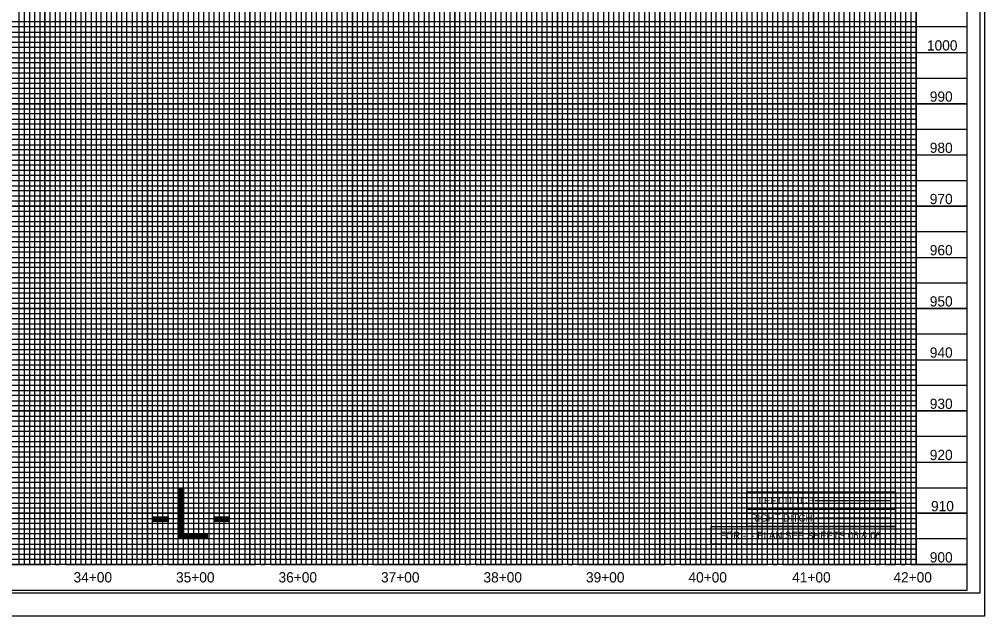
# Model space of a CAD drawing. Extents: x 1262239 to 1263984, y 747221 to 748321.
# Drawn here: x 1262981 to 1263923, y 747221 to 747803 of the extents above; entities that cross this region are included whole.
import ezdxf

# ---------------------------------------------------------------- set-up
doc = ezdxf.new("R2010")
doc.units = 0
for name, color, linetype in [('Pattern 1', 7, 'Continuous'), ('Pattern 2', 7, 'Continuous'), ('Prop Approach Slab', 7, 'Continuous'), ('Prop Drainage Structure Bridge Opening', 7, 'Continuous'), ('Prop Drainage Structure Bridge Opening Label', 7, 'Continuous'), ('Prop Erosion Rip Rap Single Stone CELL', 7, 'Continuous'), ('Prop Grid Mask', 7, 'Continuous'), ('Prop Horizontal Alignment Curve and Spiral Data', 7, 'Continuous'), ('Prop Paved Shoulder', 7, 'Continuous'), ('Prop PFL Text', 7, 'Continuous'), ('Prop Terminator CELL', 7, 'Continuous'), ('Prop Vertical Profile Strip Grade', 7, 'Continuous'), ('Prop VPI Label', 7, 'Continuous'), ('Sheet Border Standard 30in CELL', 7, 'Continuous'), ('Sheet Profile Grid Middle CELL', 7, 'Continuous'), ('Sheet Sticker Exception Certification CELL', 7, 'Continuous')]:
    doc.layers.add(name, color=color, linetype=linetype)

msp = doc.modelspace()

# ---------------------------------------------------------------- linework, layer by layer
at = {"layer": 'Pattern 1'}
for points in [[(1262955.75, 747270.74), (1263005.75, 747270.74), (1263005.75, 748295.74)], [(1263055.75, 748295.74), (1263055.75, 747270.74), (1263105.75, 747270.74), (1263105.75, 748295.74)], [(1263155.75, 748295.74), (1263155.75, 747270.74), (1263205.75, 747270.74), (1263205.75, 748295.74)], [(1263255.75, 748295.74), (1263255.75, 747270.74), (1263305.75, 747270.74), (1263305.75, 748295.74)], [(1263355.75, 748295.74), (1263355.75, 747270.74), (1263405.75, 747270.74), (1263405.75, 748295.74)], [(1263455.75, 748295.74), (1263455.75, 747270.74), (1263505.75, 747270.74), (1263505.75, 748295.74)], [(1263555.75, 748295.74), (1263555.75, 747270.74), (1263605.75, 747270.74), (1263605.75, 748245.74)], [(1263655.75, 748245.74), (1263655.75, 747270.74), (1263705.75, 747270.74), (1263705.75, 748245.74)], [(1263755.75, 748134.69), (1263755.75, 747270.74), (1263805.75, 747270.74), (1263805.75, 748134.69)], [(1263855.75, 748134.69), (1263855.75, 747270.74), (1263905.75, 747270.74)], [(1263905.75, 747720.74), (1262405.75, 747720.74), (1262405.75, 747770.74), (1263905.75, 747770.74)], [(1263905.75, 747620.74), (1262405.75, 747620.74), (1262405.75, 747670.74), (1263905.75, 747670.74)], [(1263905.75, 747520.74), (1262405.75, 747520.74), (1262405.75, 747570.74), (1263905.75, 747570.74)], [(1263905.75, 747420.74), (1262405.75, 747420.74), (1262405.75, 747470.74), (1263905.75, 747470.74)], [(1263905.75, 747320.74), (1262405.75, 747320.74), (1262405.75, 747370.74), (1263905.75, 747370.74)]]:
    msp.add_lwpolyline(points, dxfattribs=at)
at = {"layer": 'Pattern 2'}
for points in [[(1262930.75, 747270.74), (1262980.75, 747270.74), (1262980.75, 748295.74)], [(1263030.75, 748295.74), (1263030.75, 747270.74), (1263080.75, 747270.74), (1263080.75, 748295.74)], [(1263130.75, 748295.74), (1263130.75, 747270.74), (1263180.75, 747270.74), (1263180.75, 748295.74)], [(1263230.75, 748295.74), (1263230.75, 747270.74), (1263280.75, 747270.74), (1263280.75, 748295.74)], [(1263330.75, 748295.74), (1263330.75, 747270.74), (1263380.75, 747270.74), (1263380.75, 748295.74)], [(1263430.75, 748295.74), (1263430.75, 747270.74), (1263480.75, 747270.74), (1263480.75, 748295.74)], [(1263530.75, 748295.74), (1263530.75, 747270.74), (1263580.75, 747270.74), (1263580.75, 748295.74)], [(1263630.75, 748245.74), (1263630.75, 747270.74), (1263680.75, 747270.74), (1263680.75, 748245.74)], [(1263730.75, 748134.69), (1263730.75, 747270.74), (1263780.75, 747270.74), (1263780.75, 748134.69)], [(1263830.75, 748134.69), (1263830.75, 747270.74)], [(1263905.75, 747795.74), (1262405.75, 747795.74), (1262405.75, 747745.74), (1263905.75, 747745.74)], [(1263905.75, 747695.74), (1262405.75, 747695.74), (1262405.75, 747645.74), (1263905.75, 747645.74)], [(1263905.75, 747595.74), (1262405.75, 747595.74), (1262405.75, 747545.74), (1263905.75, 747545.74)], [(1263905.75, 747495.74), (1262405.75, 747495.74), (1262405.75, 747445.74), (1263905.75, 747445.74)], [(1263905.75, 747395.74), (1262405.75, 747395.74), (1262405.75, 747345.74), (1263905.75, 747345.74)], [(1263905.75, 747295.74), (1262405.75, 747295.74)]]:
    msp.add_lwpolyline(points, dxfattribs=at)
at = {"layer": 'Prop Approach Slab'}
msp.add_line((1263757.4, 747316.24), (1263830.39, 747316.24), dxfattribs=at)
at = {"layer": 'Prop Drainage Structure Bridge Opening'}
msp.add_line((1262238.75, 747220.74), (1263922.75, 747220.74), dxfattribs=at)
at = {"layer": 'Prop Drainage Structure Bridge Opening Label'}
msp.add_line((1263757.36, 747333.24), (1263830.35, 747333.24), dxfattribs=at)
at = {"layer": 'Prop Erosion Rip Rap Single Stone CELL'}
for points in [[(1263690.75, 747341.74), (1263835.71, 747341.74), (1263835.71, 747324.74), (1263690.75, 747324.74)], [(1263690.75, 747324.74), (1263835.75, 747324.74), (1263835.75, 747307.74), (1263690.75, 747307.74)]]:
    msp.add_lwpolyline(points, close=True, dxfattribs=at)
at = {"layer": 'Prop Grid Mask'}
msp.add_lwpolyline([(1262455.75, 748295.74), (1263705.7, 748295.74), (1263705.7, 748134.69), (1263855.75, 748134.69), (1263855.75, 747270.74), (1262455.75, 747270.74)], close=True, dxfattribs=at)
at = {"layer": 'Prop Paved Shoulder'}
msp.add_line((1263905.75, 747270.74), (1262405.75, 747270.74), dxfattribs=at)
msp.add_lwpolyline([(1263905.75, 748295.74), (1262405.75, 748295.74), (1262405.75, 747245.74), (1263905.75, 747245.74)], close=True, dxfattribs=at)
at = {"layer": 'Prop PFL Text'}
for p, q in [((1263005.75, 748295.74), (1263005.75, 747270.74)), ((1263055.75, 748295.74), (1263055.75, 747270.74)), ((1263105.75, 748295.74), (1263105.75, 747270.74)), ((1263155.75, 748295.74), (1263155.75, 747270.74)), ((1263205.75, 748295.74), (1263205.75, 747270.74)), ((1263255.75, 748295.74), (1263255.75, 747270.74)), ((1263305.75, 748295.74), (1263305.75, 747270.74)), ((1263355.75, 748295.74), (1263355.75, 747270.74)), ((1263405.75, 748295.74), (1263405.75, 747270.74)), ((1263455.75, 748295.74), (1263455.75, 747270.74)), ((1263505.75, 748295.74), (1263505.75, 747270.74)), ((1263555.75, 748295.74), (1263555.75, 747270.74)), ((1263605.75, 748295.74), (1263605.75, 747270.74)), ((1263655.75, 748245.74), (1263655.75, 747270.74)), ((1263705.75, 747270.74), (1263705.75, 748158.19)), ((1263755.75, 747270.74), (1263755.75, 748134.69)), ((1263805.75, 747270.74), (1263805.75, 748134.69)), ((1263855.75, 747270.74), (1263855.75, 748134.69)), ((1262405.75, 747770.74), (1263905.75, 747770.74)), ((1262405.75, 747720.74), (1263905.75, 747720.74)), ((1262405.75, 747670.74), (1263905.75, 747670.74)), ((1262405.75, 747620.74), (1263905.75, 747620.74)), ((1262405.75, 747570.74), (1263905.75, 747570.74)), ((1262405.75, 747520.74), (1263905.75, 747520.74)), ((1262405.75, 747470.74), (1263905.75, 747470.74)), ((1262405.75, 747420.74), (1263905.75, 747420.74)), ((1262405.75, 747370.74), (1263905.75, 747370.74)), ((1262405.75, 747320.74), (1263905.75, 747320.74))]:
    msp.add_line(p, q, dxfattribs=at)
at = {"layer": 'Prop Terminator CELL'}
msp.add_lwpolyline([(1263918.25, 748298.29), (1262251.75, 748298.29), (1262251.75, 747243.19), (1263918.25, 747243.19)], close=True, dxfattribs=at)
at = {"layer": 'Prop VPI Label'}
msp.add_lwpolyline([(1263922.75, 748320.74), (1262238.75, 748320.74), (1262238.75, 747220.74), (1263922.75, 747220.74)], close=True, dxfattribs=at)
at = {"layer": 'Sheet Profile Grid Middle CELL'}
msp.add_lwpolyline([(1263655.75, 747307.74), (1263835.75, 747307.74), (1263835.75, 747290.74), (1263655.75, 747290.74)], close=True, dxfattribs=at)
at = {"layer": 'Sheet Sticker Exception Certification CELL'}
for points in [[(1262985.75, 747270.74), (1262985.75, 748295.74)], [(1262990.75, 748295.74), (1262990.75, 747270.74), (1262995.75, 747270.74), (1262995.75, 748295.74)], [(1263000.75, 748295.74), (1263000.75, 747270.74), (1263010.75, 747270.74), (1263010.75, 748295.74)], [(1263015.75, 748295.74), (1263015.75, 747270.74), (1263015.75, 747270.74), (1263020.75, 747270.74), (1263020.75, 748295.74)], [(1263025.75, 748295.74), (1263025.75, 747270.74), (1263035.75, 747270.74), (1263035.75, 748295.74)], [(1263040.75, 748295.74), (1263040.75, 747270.74), (1263045.75, 747270.74), (1263045.75, 748295.74)], [(1263050.75, 748295.74), (1263050.75, 747270.74), (1263060.75, 747270.74), (1263060.75, 748295.74)], [(1263065.75, 748295.74), (1263065.75, 747270.74), (1263070.75, 747270.74), (1263070.75, 748295.74)], [(1263075.75, 748295.74), (1263075.75, 747270.74), (1263085.75, 747270.74), (1263085.75, 748295.74)], [(1263090.75, 748295.74), (1263090.75, 747270.74), (1263095.75, 747270.74), (1263095.75, 748295.74)], [(1263100.75, 748295.74), (1263100.75, 747270.74), (1263110.75, 747270.74), (1263110.75, 748295.74)], [(1263115.75, 748295.74), (1263115.75, 747270.74), (1263120.75, 747270.74), (1263120.75, 748295.74)], [(1263125.75, 748295.74), (1263125.75, 747270.74), (1263135.75, 747270.74), (1263135.75, 748295.74)], [(1263140.75, 748295.74), (1263140.75, 747270.74), (1263145.75, 747270.74), (1263145.75, 748295.74)], [(1263150.75, 748295.74), (1263150.75, 747270.74), (1263160.75, 747270.74), (1263160.75, 748295.74)], [(1263165.75, 748295.74), (1263165.75, 747270.74)], [(1263165.75, 747270.74), (1263170.75, 747270.74), (1263170.75, 748295.14)], [(1263175.75, 748295.14), (1263175.75, 747270.74), (1263185.75, 747270.74), (1263185.75, 748295.74)], [(1263190.75, 748295.74), (1263190.75, 747270.74), (1263195.75, 747270.74), (1263195.75, 748295.74)], [(1263200.75, 748295.74), (1263200.75, 747270.74), (1263210.75, 747270.74), (1263210.75, 748295.74)], [(1263215.75, 748295.74), (1263215.75, 747270.74), (1263220.75, 747270.74), (1263220.75, 748295.74)], [(1263225.75, 748295.74), (1263225.75, 747270.74), (1263235.75, 747270.74), (1263235.75, 748295.74)], [(1263240.75, 748295.74), (1263240.75, 747270.74), (1263245.75, 747270.74), (1263245.75, 748295.74)], [(1263250.75, 748295.74), (1263250.75, 747270.74), (1263260.75, 747270.74), (1263260.75, 748295.74)], [(1263265.75, 748295.74), (1263265.75, 747270.74), (1263270.75, 747270.74), (1263270.75, 748295.74)], [(1263275.75, 748295.74), (1263275.75, 747270.74), (1263285.75, 747270.74), (1263285.75, 748295.74)], [(1263290.75, 748295.74), (1263290.75, 747270.74), (1263295.75, 747270.74), (1263295.75, 748295.74)], [(1263300.75, 748295.74), (1263300.75, 747270.74), (1263310.75, 747270.74), (1263310.75, 748295.74)], [(1263315.75, 748295.74), (1263315.75, 747270.74), (1263320.75, 747270.74), (1263320.75, 748295.74)], [(1263325.75, 748295.74), (1263325.75, 747270.74), (1263335.75, 747270.74), (1263335.75, 748295.74)], [(1263340.75, 748295.74), (1263340.75, 747270.74), (1263345.75, 747270.74), (1263345.75, 748295.74)], [(1263350.75, 748295.74), (1263350.75, 747270.74), (1263360.75, 747270.74), (1263360.75, 748295.74)], [(1263365.75, 748295.74), (1263365.75, 747270.74), (1263370.75, 747270.74), (1263370.75, 748295.74)], [(1263375.75, 748295.74), (1263375.75, 747270.74), (1263385.75, 747270.74), (1263385.75, 748295.74)], [(1263390.75, 748295.74), (1263390.75, 747270.74), (1263395.75, 747270.74), (1263395.75, 748295.74)], [(1263400.75, 748295.74), (1263400.75, 747270.74), (1263410.75, 747270.74), (1263410.75, 748295.74)], [(1263415.75, 748295.74), (1263415.75, 747270.74), (1263420.75, 747270.74), (1263420.75, 748295.74)], [(1263425.75, 748295.74), (1263425.75, 747270.74), (1263435.75, 747270.74), (1263435.75, 748295.74)], [(1263440.75, 748295.74), (1263440.75, 747270.74), (1263445.75, 747270.74), (1263445.75, 748295.74)], [(1263450.75, 748295.74), (1263450.75, 747270.74), (1263460.75, 747270.74), (1263460.75, 748295.74)], [(1263465.75, 748295.74), (1263465.75, 747270.74), (1263470.75, 747270.74), (1263470.75, 748295.74)], [(1263475.75, 748295.74), (1263475.75, 747270.74)], [(1263475.75, 747270.74), (1263485.75, 747270.74), (1263485.75, 748295.74)], [(1263490.75, 748295.74), (1263490.75, 747270.74), (1263495.75, 747270.74), (1263495.75, 748295.74)], [(1263500.75, 748295.74), (1263500.75, 747270.74), (1263510.75, 747270.74), (1263510.75, 748295.74)], [(1263515.75, 748295.74), (1263515.75, 747270.74), (1263520.75, 747270.74), (1263520.75, 748295.74)], [(1263525.75, 748295.74), (1263525.75, 747270.74), (1263535.75, 747270.74), (1263535.75, 748295.74)], [(1263540.75, 748295.74), (1263540.75, 747270.74), (1263545.75, 747270.74), (1263545.75, 748295.74)], [(1263550.75, 748295.74), (1263550.75, 747270.74), (1263560.75, 747270.74), (1263560.75, 748295.74)], [(1263565.75, 748295.74), (1263565.75, 747270.74), (1263570.75, 747270.74), (1263570.75, 748295.74)], [(1263575.75, 748295.74), (1263575.75, 747270.74), (1263585.75, 747270.74), (1263585.75, 748295.74)], [(1263590.75, 748295.74), (1263590.75, 747270.74), (1263595.75, 747270.74), (1263595.75, 748295.74)], [(1263600.75, 748295.74), (1263600.75, 747270.74), (1263610.75, 747270.74), (1263610.75, 748245.74)], [(1263615.75, 748245.74), (1263615.75, 747270.74), (1263620.75, 747270.74), (1263620.75, 748245.74)], [(1263625.75, 748245.74), (1263625.75, 747270.74), (1263635.75, 747270.74), (1263635.75, 748245.74)], [(1263640.75, 748245.74), (1263640.75, 747270.74), (1263645.75, 747270.74), (1263645.75, 748245.74)], [(1263650.75, 748245.74), (1263650.75, 747270.74), (1263660.75, 747270.74), (1263660.75, 748245.74)], [(1263665.75, 748245.74), (1263665.75, 747270.74), (1263670.75, 747270.74), (1263670.75, 748245.74)], [(1263675.75, 748245.74), (1263675.75, 747270.74), (1263685.75, 747270.74), (1263685.75, 748245.74)], [(1263690.75, 748245.74), (1263690.75, 747270.74), (1263695.75, 747270.74), (1263695.75, 748245.74)], [(1263700.75, 748245.74), (1263700.75, 747270.74), (1263710.75, 747270.74), (1263710.75, 748134.69)], [(1263715.75, 748134.69), (1263715.75, 747270.74), (1263720.75, 747270.74), (1263720.75, 748134.69)], [(1263725.75, 748134.69), (1263725.75, 747270.74), (1263735.75, 747270.74), (1263735.75, 748134.69)], [(1263740.75, 748134.69), (1263740.75, 747270.74), (1263745.75, 747270.74), (1263745.75, 748134.69)], [(1263750.75, 748134.69), (1263750.75, 747270.74), (1263760.75, 747270.74), (1263760.75, 748134.69)], [(1263765.75, 748134.69), (1263765.75, 747270.74), (1263770.75, 747270.74), (1263770.75, 748134.69)], [(1263775.75, 748134.69), (1263775.75, 747270.74), (1263785.75, 747270.74), (1263785.75, 748134.69)], [(1263790.75, 748134.69), (1263790.75, 747270.74)], [(1263790.75, 747270.74), (1263795.75, 747270.74), (1263795.75, 748134.69)], [(1263800.75, 748134.69), (1263800.75, 747270.74), (1263810.75, 747270.74), (1263810.75, 748134.69)], [(1263815.75, 748134.69), (1263815.75, 747270.74), (1263820.75, 747270.74), (1263820.75, 748134.69)], [(1263825.75, 748134.69), (1263825.75, 747270.74), (1263835.75, 747270.74), (1263835.75, 748134.69)], [(1263840.75, 748134.69), (1263840.75, 747270.74), (1263845.75, 747270.74), (1263845.75, 748134.69)], [(1263850.75, 748134.69), (1263850.75, 747270.74), (1263860.75, 747270.74)], [(1263855.75, 747800.74), (1262455.75, 747800.74), (1262455.75, 747790.74), (1263855.75, 747790.74)], [(1263855.75, 747785.74), (1262455.75, 747785.74), (1262455.75, 747780.74), (1263855.75, 747780.74)], [(1263855.75, 747775.74), (1262455.75, 747775.74)], [(1262455.75, 747765.74), (1263855.75, 747765.74)], [(1263855.75, 747760.74), (1262455.75, 747760.74), (1262455.75, 747755.74), (1263855.75, 747755.74)], [(1263855.75, 747750.74), (1262455.75, 747750.74), (1262455.75, 747740.74), (1263855.75, 747740.74)], [(1263855.75, 747735.74), (1262455.75, 747735.74), (1262455.75, 747730.74), (1263855.75, 747730.74)], [(1263855.75, 747725.74), (1262455.75, 747725.74), (1262455.75, 747715.74), (1263855.75, 747715.74)], [(1263855.75, 747710.74), (1262455.75, 747710.74), (1262455.75, 747705.74), (1263855.75, 747705.74)], [(1263855.75, 747700.74), (1262455.75, 747700.74), (1262455.75, 747690.74), (1263855.75, 747690.74)], [(1263855.75, 747685.74), (1262455.75, 747685.74), (1262455.75, 747680.74), (1263855.75, 747680.74)], [(1263855.75, 747675.74), (1262455.75, 747675.74), (1262455.75, 747665.74), (1263855.75, 747665.74)], [(1263855.75, 747660.74), (1262455.75, 747660.74), (1262455.75, 747655.74), (1263855.75, 747655.74)], [(1263855.75, 747650.74), (1262455.75, 747650.74), (1262455.75, 747640.74), (1263855.75, 747640.74)], [(1263855.75, 747635.74), (1262455.75, 747635.74), (1262455.75, 747630.74), (1263855.75, 747630.74)], [(1263855.75, 747625.74), (1262455.75, 747625.74), (1262455.75, 747615.74), (1263855.75, 747615.74)], [(1263855.75, 747610.74), (1262455.75, 747610.74), (1262455.75, 747605.74), (1263855.75, 747605.74)], [(1263855.75, 747600.74), (1262455.75, 747600.74), (1262455.75, 747590.74), (1263855.75, 747590.74)], [(1263855.75, 747585.74), (1262455.75, 747585.74), (1262455.75, 747580.74), (1263855.75, 747580.74)], [(1263855.75, 747575.74), (1262455.75, 747575.74), (1262455.75, 747565.74), (1263855.75, 747565.74)], [(1263855.75, 747560.74), (1262455.75, 747560.74), (1262455.75, 747555.74), (1263855.75, 747555.74)], [(1263855.75, 747550.74), (1262455.75, 747550.74), (1262455.75, 747540.74), (1263855.75, 747540.74)], [(1263855.75, 747535.74), (1262455.75, 747535.74), (1262455.75, 747530.74), (1263855.75, 747530.74)], [(1263855.75, 747525.74), (1262455.75, 747525.74), (1262455.75, 747515.74), (1263855.75, 747515.74)], [(1263855.75, 747510.74), (1262455.75, 747510.74), (1262455.75, 747505.74), (1263855.75, 747505.74)], [(1263855.75, 747500.74), (1262455.75, 747500.74), (1262455.75, 747490.74), (1263855.75, 747490.74)], [(1263855.75, 747485.74), (1262455.75, 747485.74), (1262455.75, 747480.74), (1263855.75, 747480.74)], [(1263855.75, 747475.74), (1262455.75, 747475.74)], [(1262455.75, 747465.74), (1263855.75, 747465.74)], [(1263855.75, 747460.74), (1262455.75, 747460.74), (1262455.75, 747455.74), (1263855.75, 747455.74)], [(1263855.75, 747450.74), (1262455.75, 747450.74)], [(1262455.75, 747440.74), (1263855.75, 747440.74)], [(1263855.75, 747435.74), (1262455.75, 747435.74), (1262455.75, 747430.74), (1263855.75, 747430.74)], [(1263855.75, 747425.74), (1262455.75, 747425.74), (1262455.75, 747415.74), (1263855.75, 747415.74)], [(1263855.75, 747410.74), (1262455.75, 747410.74), (1262455.75, 747405.74), (1263855.75, 747405.74)], [(1263855.75, 747400.74), (1262455.75, 747400.74), (1262455.75, 747390.74), (1263855.75, 747390.74)], [(1263855.75, 747385.74), (1262455.75, 747385.74), (1262455.75, 747380.74), (1263855.75, 747380.74)], [(1263855.75, 747375.74), (1262455.75, 747375.74), (1262455.75, 747365.74), (1263855.75, 747365.74)], [(1263855.75, 747360.74), (1262455.75, 747360.74), (1262455.75, 747355.74), (1263855.75, 747355.74)], [(1263855.75, 747350.74), (1262455.75, 747350.74), (1262455.75, 747340.74), (1263855.75, 747340.74)], [(1263855.75, 747335.74), (1262455.75, 747335.74), (1262455.75, 747330.74), (1263855.75, 747330.74)], [(1263855.75, 747325.74), (1262455.75, 747325.74), (1262455.75, 747315.74), (1263855.75, 747315.74)], [(1263855.75, 747310.74), (1262455.75, 747310.74), (1262455.75, 747305.74), (1263855.75, 747305.74)], [(1263855.75, 747300.74), (1262455.75, 747300.74), (1262455.75, 747290.74), (1263855.75, 747290.74)], [(1263855.75, 747285.74), (1262455.75, 747285.74), (1262455.75, 747280.74), (1263855.75, 747280.74)], [(1263855.75, 747275.74), (1262455.75, 747275.74)]]:
    msp.add_lwpolyline(points, dxfattribs=at)

# ---------------------------------------------------------------- texts
at = {"layer": 'Prop Erosion Rip Rap Single Stone CELL'}
for s, p in [('LEFT DITCH', (1263702.19, 747329.73)), ('RIGHT DITCH', (1263694.28, 747312.73)), ('FOR -L- PLAN SEE SHEETS 05 & 06', (1263664.42, 747295.74))]:
    msp.add_text(s, height=7, dxfattribs=at).set_placement(p)
at = {"layer": 'Prop Horizontal Alignment Curve and Spiral Data'}
for s, p in [('34+00', (1263033.69, 747253.24)), ('35+00', (1263133.69, 747253.24)), ('36+00', (1263233.69, 747253.24)), ('37+00', (1263333.69, 747253.24)), ('38+00', (1263433.69, 747253.24)), ('39+00', (1263533.69, 747253.24)), ('40+00', (1263633.69, 747253.24)), ('41+00', (1263734.88, 747253.24)), ('42+00', (1263833.69, 747253.24))]:
    msp.add_text(s, height=10, dxfattribs=at).set_placement(p)
at = {"layer": 'Prop Vertical Profile Strip Grade'}
for s, p in [('1000', (1263866.43, 747772.74)), ('990', (1263869.19, 747722.74)), ('980', (1263869.19, 747672.74)), ('970', (1263869.19, 747622.74)), ('960', (1263869.19, 747572.74)), ('950', (1263869.19, 747522.74)), ('940', (1263869.19, 747472.74)), ('930', (1263869.19, 747422.74)), ('920', (1263869.19, 747372.74)), ('910', (1263870.38, 747322.74)), ('900', (1263869.19, 747272.74))]:
    msp.add_text(s, height=10, dxfattribs=at).set_placement(p)
at = {"layer": 'Sheet Border Standard 30in CELL'}
msp.add_text('-L-', height=50, dxfattribs=at).set_placement((1263107.65, 747295.74))

doc.saveas('drawing.dxf')
